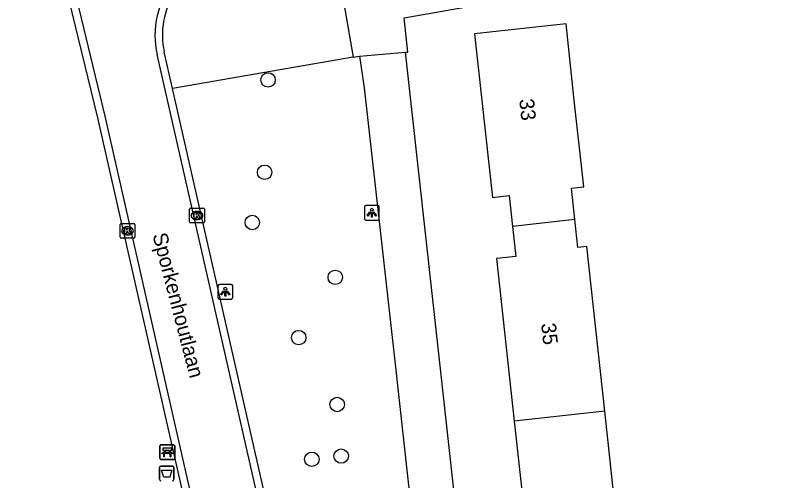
# Model space of a CAD drawing. Extents: x 162675 to 163482, y 379761 to 381227.
# Drawn here: x 162905.2 to 162956.8, y 380381.6 to 380413.2 of the extents above; entities that cross this region are included whole.
import ezdxf

# ---------------------------------------------------------------- set-up
doc = ezdxf.new("R2010")
doc.units = 0
for name, color, linetype in [('IMGEO_Afvalbak', 7, 'Continuous'), ('IMGEO_Bank', 7, 'Continuous'), ('IMGEO_Boom', 7, 'Continuous'), ('IMGEO_Kolk', 7, 'Continuous'), ('IMGEO_Lichtpunt', 7, 'Continuous'), ('IMGEO_Openbare_ruimte_label', 7, 'Continuous'), ('IMGEO_Pand', 7, 'Continuous'), ('IMGEO_Pand_nummerreeks', 7, 'Continuous'), ('IMGEO_Parkeervlak_open', 7, 'Continuous'), ('IMGEO_Rijbaan_lokaal_gesloten', 7, 'Continuous'), ('IMGEO_Rijbaan_lokaal_open', 7, 'Continuous'), ('IMGEO_Voetpad_open', 7, 'Continuous')]:
    doc.layers.add(name, color=color, linetype=linetype)

msp = doc.modelspace()

# ---------------------------------------------------------------- linework, layer by layer
at = {"layer": 'IMGEO_Afvalbak'}
for p, q in [((162914.961, 380381.672), (162914.961, 380382.472)), ((162914.961, 380382.472), (162914.961, 380381.672)), ((162915.061, 380382.572), (162915.851, 380382.572)), ((162915.851, 380382.572), (162915.061, 380382.572)), ((162915.951, 380382.472), (162915.951, 380381.672)), ((162915.951, 380381.672), (162915.951, 380382.472))]:
    msp.add_line(p, q, dxfattribs=at)
msp.add_lwpolyline([(162915.104, 380382.286), (162915.808, 380382.286), (162915.659, 380381.816), (162915.253, 380381.816), (162915.104, 380382.286)], dxfattribs=at)
for centre, start, end in [((162915.061, 380382.472), 90, 180), ((162915.061, 380382.472), 90, 180), ((162915.851, 380382.472), 0, 90), ((162915.851, 380382.472), 360, 90), ((162915.061, 380381.672), 180, 270), ((162915.061, 380381.672), 180, 270), ((162915.851, 380381.672), 270, 0), ((162915.851, 380381.672), 270, 0)]:
    msp.add_arc(centre, 0.1, start, end, dxfattribs=at)
at = {"layer": 'IMGEO_Bank'}
for p, q in [((162914.998, 380383.095), (162914.998, 380383.936)), ((162914.998, 380383.936), (162914.998, 380383.095)), ((162915.073, 380384.02), (162915.914, 380384.02)), ((162915.914, 380384.02), (162915.073, 380384.02)), ((162915.998, 380383.945), (162915.998, 380383.104)), ((162915.998, 380383.104), (162915.998, 380383.945)), ((162915.695, 380383.418), (162915.302, 380383.418)), ((162915.307, 380383.526), (162915.307, 380383.632)), ((162915.351, 380383.632), (162915.351, 380383.526)), ((162915.639, 380383.638), (162915.357, 380383.638)), ((162915.357, 380383.52), (162915.639, 380383.52)), ((162915.645, 380383.526), (162915.645, 380383.632)), ((162915.689, 380383.632), (162915.689, 380383.526)), ((162915.923, 380383.02), (162915.082, 380383.02)), ((162915.082, 380383.02), (162915.923, 380383.02))]:
    msp.add_line(p, q, dxfattribs=at)
for points in [[(162915.301, 380383.638), (162915.215, 380383.638), (162915.215, 380383.799), (162915.778, 380383.799), (162915.778, 380383.638), (162915.695, 380383.638)], [(162915.245, 380383.418), (162915.103, 380383.418), (162915.215, 380383.52), (162915.301, 380383.52)], [(162915.295, 380383.411), (162915.295, 380383.204), (162915.252, 380383.204), (162915.252, 380383.411)], [(162915.695, 380383.52), (162915.778, 380383.52), (162915.89, 380383.418), (162915.751, 380383.418)], [(162915.745, 380383.411), (162915.745, 380383.204), (162915.701, 380383.204), (162915.701, 380383.411)]]:
    msp.add_lwpolyline(points, dxfattribs=at)
for centre, radius, start, end in [((162915.076, 380383.942), 0.0779, 92.4484, 184.2845), ((162915.076, 380383.942), 0.0779, 92.4484, 184.2845), ((162915.92, 380383.942), 0.0779, 2.4484, 94.2845), ((162915.92, 380383.942), 0.0779, 2.4484, 94.2845), ((162915.245, 380383.411), 0.00671, 2.8957, 87.1043), ((162915.302, 380383.411), 0.00671, 92.8957, 177.1043), ((162915.3, 380383.631), 0.00671, 2.8957, 87.1043), ((162915.3, 380383.527), 0.00671, 272.8957, 357.1043), ((162915.357, 380383.631), 0.00671, 92.8957, 177.1043), ((162915.357, 380383.527), 0.00671, 182.8957, 267.1043), ((162915.639, 380383.631), 0.00671, 2.8957, 87.1043), ((162915.639, 380383.527), 0.00671, 272.8957, 357.1043), ((162915.696, 380383.631), 0.00671, 92.8957, 177.1043), ((162915.696, 380383.527), 0.00671, 182.8957, 267.1043), ((162915.694, 380383.411), 0.00671, 2.8957, 87.1043), ((162915.751, 380383.411), 0.00671, 92.8957, 177.1043), ((162915.076, 380383.098), 0.0779, 182.4484, 274.2845), ((162915.076, 380383.098), 0.0779, 182.4484, 274.2845), ((162915.92, 380383.098), 0.0779, 272.4484, 4.2845), ((162915.92, 380383.098), 0.0779, 272.4484, 4.2845)]:
    msp.add_arc(centre, radius, start, end, dxfattribs=at)
at = {"layer": 'IMGEO_Boom'}
for centre in [(162922.327, 380408.762), (162922.095, 380402.501), (162921.256, 380399.092), (162926.886, 380395.374), (162924.41, 380391.284), (162927.014, 380386.75), (162925.298, 380383.032), (162927.286, 380383.246)]:
    msp.add_circle(centre, 0.489, dxfattribs=at)
at = {"layer": 'IMGEO_Kolk'}
for p, q in [((162917.007, 380399.144), (162917.007, 380399.996)), ((162917.082, 380400.07), (162917.934, 380400.07)), ((162917.495, 380399.85), (162917.52, 380399.85)), ((162918.008, 380399.996), (162918.008, 380399.144)), ((162917.518, 380399.29), (162917.493, 380399.29)), ((162912.296, 380398.107), (162912.296, 380398.959)), ((162912.371, 380399.033), (162913.223, 380399.033)), ((162912.784, 380398.813), (162912.809, 380398.813)), ((162913.297, 380398.959), (162913.297, 380398.107)), ((162917.934, 380399.07), (162917.082, 380399.07)), ((162912.807, 380398.253), (162912.782, 380398.253)), ((162913.223, 380398.033), (162912.371, 380398.033))]:
    msp.add_line(p, q, dxfattribs=at)
for points in [[(162917.007, 380399.144), (162917.007, 380399.996)], [(162917.082, 380400.07), (162917.934, 380400.07)], [(162917.328, 380399.77), (162917.451, 380399.77), (162917.451, 380399.619), (162917.581, 380399.77), (162917.745, 380399.77), (162917.599, 380399.619), (162917.752, 380399.37), (162917.6, 380399.37), (162917.515, 380399.534), (162917.451, 380399.467), (162917.451, 380399.37), (162917.328, 380399.37), (162917.328, 380399.77)], [(162918.008, 380399.996), (162918.008, 380399.144)], [(162912.296, 380398.107), (162912.296, 380398.959)], [(162912.371, 380399.033), (162913.223, 380399.033)], [(162912.617, 380398.733), (162912.74, 380398.733), (162912.74, 380398.582), (162912.87, 380398.733), (162913.034, 380398.733), (162912.888, 380398.582), (162913.041, 380398.333), (162912.889, 380398.333), (162912.804, 380398.497), (162912.74, 380398.43), (162912.74, 380398.333), (162912.617, 380398.333), (162912.617, 380398.733)], [(162913.297, 380398.959), (162913.297, 380398.107)], [(162917.934, 380399.07), (162917.082, 380399.07)], [(162913.223, 380398.033), (162912.371, 380398.033)]]:
    msp.add_lwpolyline(points, dxfattribs=at)
for centre, start, end in [((162917.084, 380399.994), 91.552, 178.448), ((162917.084, 380399.994), 91.552, 178.448), ((162917.932, 380399.994), 1.552, 88.448), ((162917.932, 380399.994), 1.552, 88.448), ((162912.373, 380398.957), 91.552, 178.448), ((162912.373, 380398.957), 91.552, 178.448), ((162913.221, 380398.957), 1.552, 88.448), ((162913.221, 380398.957), 1.552, 88.448), ((162917.084, 380399.146), 181.552, 268.448), ((162917.084, 380399.146), 181.552, 268.448), ((162917.932, 380399.146), 271.552, 358.448), ((162917.932, 380399.146), 271.552, 358.448), ((162912.373, 380398.109), 181.552, 268.448), ((162912.373, 380398.109), 181.552, 268.448), ((162913.221, 380398.109), 271.552, 358.448), ((162913.221, 380398.109), 271.552, 358.448)]:
    msp.add_arc(centre, 0.0765, start, end, dxfattribs=at)
for centre, major_axis, ratio, start_param, end_param in [((162917.494, 380399.57), (-0.387, 0.002), 0.722429, 4.712389, 7.853982), ((162917.519, 380399.57), (-0.39, 0.002), 0.717154, 1.570796, 4.712389), ((162912.783, 380398.533), (-0.387, 0.002), 0.722429, 4.712389, 7.853982), ((162912.808, 380398.533), (-0.39, 0.002), 0.717154, 1.570796, 4.712389)]:
    msp.add_ellipse(centre, major_axis=major_axis, ratio=ratio, start_param=start_param, end_param=end_param, dxfattribs=at)
at = {"layer": 'IMGEO_Lichtpunt'}
for p, q in [((162928.864, 380400.16), (162928.864, 380399.353)), ((162928.864, 380400.16), (162928.864, 380399.353)), ((162929.766, 380400.255), (162928.958, 380400.255)), ((162929.766, 380400.255), (162928.958, 380400.255)), ((162929.86, 380399.353), (162929.86, 380400.16)), ((162929.86, 380399.353), (162929.86, 380400.16)), ((162928.958, 380399.259), (162929.766, 380399.259)), ((162928.958, 380399.259), (162929.766, 380399.259)), ((162918.933, 380394.801), (162918.933, 380393.994)), ((162918.933, 380394.801), (162918.933, 380393.994)), ((162919.835, 380394.896), (162919.027, 380394.896)), ((162919.835, 380394.896), (162919.027, 380394.896)), ((162919.929, 380393.994), (162919.929, 380394.801)), ((162919.929, 380393.994), (162919.929, 380394.801)), ((162919.027, 380393.9), (162919.835, 380393.9)), ((162919.027, 380393.9), (162919.835, 380393.9))]:
    msp.add_line(p, q, dxfattribs=at)
for points in [[(162929.238, 380399.824), (162929.277, 380399.796), (162929.089, 380399.534), (162929.051, 380399.561), (162929.238, 380399.824)], [(162929.34, 380399.776), (162929.387, 380399.776), (162929.387, 380399.454), (162929.34, 380399.454), (162929.34, 380399.776)], [(162929.45, 380399.796), (162929.488, 380399.823), (162929.675, 380399.561), (162929.636, 380399.533), (162929.45, 380399.796)], [(162919.307, 380394.465), (162919.346, 380394.437), (162919.158, 380394.175), (162919.12, 380394.202), (162919.307, 380394.465)], [(162919.409, 380394.417), (162919.456, 380394.417), (162919.456, 380394.095), (162919.409, 380394.095), (162919.409, 380394.417)], [(162919.519, 380394.437), (162919.557, 380394.464), (162919.744, 380394.202), (162919.705, 380394.174), (162919.519, 380394.437)]]:
    msp.add_lwpolyline(points, dxfattribs=at)
for centre in [(162929.363, 380399.958), (162919.432, 380394.599)]:
    msp.add_circle(centre, 0.0994, dxfattribs=at)
for centre, start, end in [((162928.958, 380400.16), 90, 180), ((162928.958, 380400.16), 90, 180), ((162929.766, 380400.16), 0, 90), ((162929.766, 380400.16), 0, 90), ((162928.958, 380399.353), 180, 270), ((162928.958, 380399.353), 180, 270), ((162929.766, 380399.353), 270, 0), ((162929.766, 380399.353), 270, 360), ((162919.027, 380394.801), 90, 180), ((162919.027, 380394.801), 90, 180), ((162919.835, 380394.801), 0, 90), ((162919.835, 380394.801), 0, 90), ((162919.027, 380393.994), 180, 270), ((162919.027, 380393.994), 180, 270), ((162919.835, 380393.994), 270, 0), ((162919.835, 380393.994), 270, 360)]:
    msp.add_arc(centre, 0.0946, start, end, dxfattribs=at)
at = {"layer": 'IMGEO_Pand'}
for points in [[(162943.129, 380399.291), (162942.897, 380401.424), (162943.734, 380401.515), (162943.072, 380407.597), (162942.531, 380412.567), (162936.334, 380411.892), (162937.542, 380400.798), (162938.68, 380400.922), (162938.908, 380398.832)], [(162943.129, 380399.291), (162938.908, 380398.832)], [(162945.155, 380386.295), (162943.939, 380397.468), (162943.335, 380397.402), (162943.129, 380399.291)], [(162938.908, 380398.832), (162939.131, 380396.783), (162937.824, 380396.641), (162939.023, 380385.627)], [(162945.155, 380386.295), (162939.023, 380385.627)], [(162945.909, 380373.16), (162945.703, 380375.057), (162946.371, 380375.13), (162945.155, 380386.295)], [(162939.023, 380385.627), (162940.248, 380374.372), (162941.398, 380374.497), (162941.595, 380372.69)]]:
    msp.add_lwpolyline(points, dxfattribs=at)
at = {"layer": 'IMGEO_Parkeervlak_open'}
msp.add_lwpolyline([(162928.107, 380410.3), (162915.849, 380408.193)], dxfattribs=at)
at = {"layer": 'IMGEO_Rijbaan_lokaal_gesloten'}
for points in [[(162905.664, 380428.582), (162908.696, 380416.996), (162911.256, 380406.295), (162922.323, 380357.573)], [(162927.957, 380352.531), (162914.799, 380410.486)]]:
    msp.add_lwpolyline(points, dxfattribs=at)
msp.add_arc((162920.522, 380411.774), 5.866, 141.0053, 192.6779, dxfattribs=at)
at = {"layer": 'IMGEO_Rijbaan_lokaal_open'}
for points in [[(162921.832, 380357.466), (162910.779, 380406.188), (162907.954, 380417.824), (162905.185, 380428.457)], [(162915.849, 380408.193), (162915.283, 380410.67)], [(162928.454, 380352.652), (162915.849, 380408.193)]]:
    msp.add_lwpolyline(points, dxfattribs=at)
msp.add_arc((162920.458, 380411.8), 5.297, 101.2683, 192.3186, dxfattribs=at)
at = {"layer": 'IMGEO_Voetpad_open'}
for points in [[(162931.642, 380410.639), (162931.807, 380410.658), (162931.554, 380412.984), (162976.014, 380420.813), (162979.334, 380421.437)], [(162926.874, 380417.363), (162928.107, 380410.3)], [(162928.521, 380410.378), (162931.642, 380410.639)], [(162937.748, 380355.281), (162934.361, 380386.086), (162931.642, 380410.639)], [(162928.107, 380410.3), (162928.521, 380410.378)], [(162928.521, 380410.378), (162928.851, 380408.226), (162930.912, 380389.894), (162934.775, 380354.805), (162935.009, 380352.675), (162935.135, 380351.536)]]:
    msp.add_lwpolyline(points, dxfattribs=at)

# ---------------------------------------------------------------- texts
at = {"layer": 'IMGEO_Openbare_ruimte_label'}
msp.add_text('Sporkenhoutlaan', height=1, rotation=284.6619, dxfattribs=at).set_placement((162914.483, 380398.251))
at = {"layer": 'IMGEO_Pand_nummerreeks'}
for s, rotation, p in [('33', 276.2143, (162939.354, 380407.44)), ('35', 276.2128, (162940.839, 380392.229))]:
    msp.add_text(s, height=1, rotation=rotation, dxfattribs=at).set_placement(p)

doc.saveas('drawing.dxf')
